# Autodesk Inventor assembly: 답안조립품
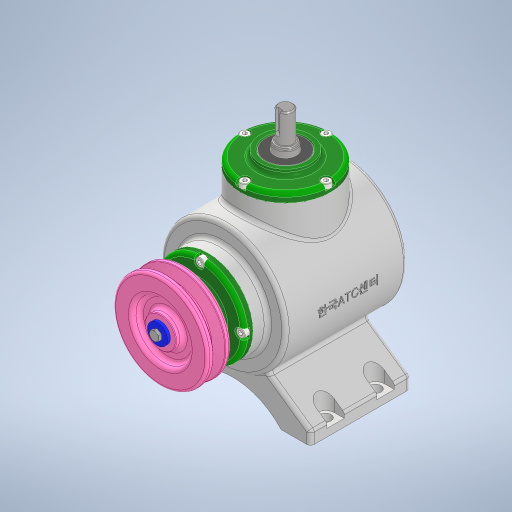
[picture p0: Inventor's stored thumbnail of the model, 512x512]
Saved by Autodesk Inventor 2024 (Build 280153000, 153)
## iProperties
Created: 2023-08
Part Number: 답안조립품
Document SubType Name: Assembly
Designer: Owner
Author: Owner
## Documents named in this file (17)
- C:\Users\Owner\Desktop\730813V1002\답안조립품.iam
- C:\Users\Owner\Desktop\730813V1002\본체.ipt
- C:\Users\Owner\Desktop\730813V1002\V-벨트풀리.ipt
- C:\Users\Owner\Desktop\730813V1002\메인 베벨기어.ipt
- C:\Users\Owner\Desktop\730813V1002\메인 축.ipt
- 메인 축.ipt
- C:\Users\Owner\Desktop\730813V1002\베어링 6203.ipt
- C:\Users\Owner\Desktop\730813V1002\볼트 M4 x 10.ipt
- C:\Users\Owner\Desktop\730813V1002\서브 베벨기어.ipt
- C:\Users\Owner\Desktop\730813V1002\서브 축.ipt
- 서브 축.ipt
- C:\Users\Owner\Desktop\730813V1002\오일실 17 x 32 x 8.ipt
- C:\Users\Owner\Desktop\730813V1002\와셔 4 x 16.ipt
- C:\Users\Owner\Desktop\730813V1002\육각볼트 M4 x 8.ipt
- C:\Users\Owner\Desktop\730813V1002\커버.ipt
- C:\Users\Owner\Desktop\730813V1002\키 4 x 4 x 14.ipt
- C:\Users\Owner\Desktop\730813V1002\키 5 x 5 x 14.ipt
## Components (1 placed, 1 different names)
1. V-벨트풀리:1
